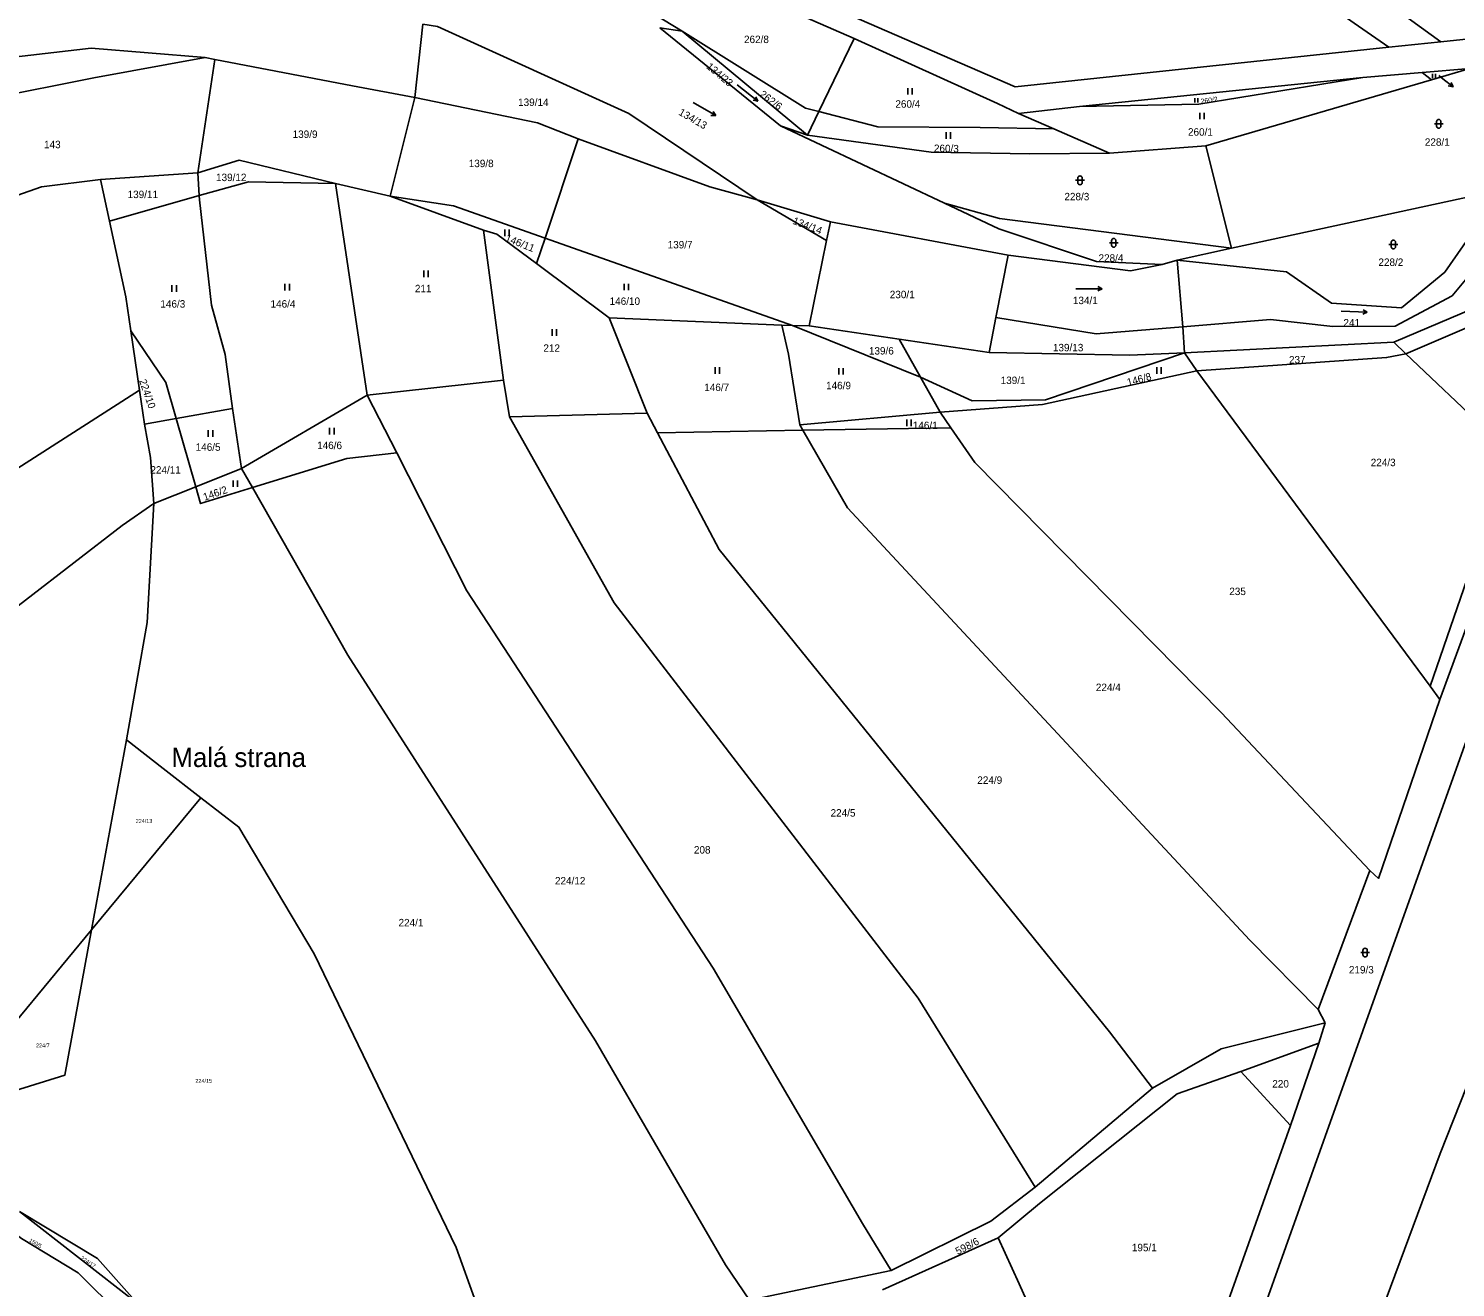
# Model space of a CAD drawing. Extents: x -758582 to -751794, y -998770 to -994350.
# Drawn here: x -755427.1 to -755100.9, y -995507.3 to -995219.5 of the extents above; entities that cross this region are included whole.
import ezdxf

# ---------------------------------------------------------------- set-up
doc = ezdxf.new("R2010")
doc.units = 0
for name, color, linetype in [('Hranice parcel', 7, 'Continuous'), ('Parcelní čísla', 7, 'Continuous'), ('Pop  PČ popisy', 7, 'Continuous'), ('Značky kultur', 7, 'Continuous')]:
    doc.layers.add(name, color=color, linetype=linetype)

msp = doc.modelspace()

# ---------------------------------------------------------------- linework, layer by layer
at = {"layer": 'Hranice parcel'}
for p, q in [((-755138.2, -995197.68), (-755104.25, -995222.48)), ((-755281.37, -995202.97), (-755238.36, -995221.7)), ((-755148.45, -995201.22), (-755116.14, -995223.73)), ((-755277.66, -995220.08), (-755288.3, -995213.59)), ((-755336.91, -995218.43), (-755338.81, -995235.22)), ((-755277.66, -995220.08), (-755282.75, -995219.3)), ((-755255.17, -995241.71), (-755282.75, -995219.3)), ((-755249, -995243.83), (-755277.66, -995220.08)), ((-755238.36, -995221.7), (-755246.41, -995238.44)), ((-755104.25, -995222.48), (-755116.14, -995223.73)), ((-755104.25, -995222.48), (-755094.22, -995221.42)), ((-755384.5, -995226.51), (-755386.67, -995226.04)), ((-755388.37, -995252.43), (-755384.5, -995226.51)), ((-755108.49, -995229.54), (-755097.59, -995228.62)), ((-755097.59, -995228.62), (-755106.35, -995231.18)), ((-755186.86, -995237.28), (-755122.08, -995230.68)), ((-755106.35, -995231.18), (-755157.96, -995246.27)), ((-755122.08, -995230.68), (-755108.49, -995229.54)), ((-755106.35, -995231.18), (-755108.49, -995229.54)), ((-755338.81, -995235.22), (-755344.39, -995257.76)), ((-755246.41, -995238.44), (-755249, -995243.83)), ((-755200.8, -995238.88), (-755186.86, -995237.28)), ((-755200.8, -995238.88), (-755192.72, -995242.36)), ((-755255.17, -995241.71), (-755249, -995243.83)), ((-755217.71, -995259.39), (-755255.17, -995241.71)), ((-755192.72, -995242.36), (-755179.99, -995247.96)), ((-755301.46, -995244.65), (-755309.01, -995267.34)), ((-755157.96, -995246.27), (-755179.99, -995247.96)), ((-755157.96, -995246.27), (-755152.13, -995269.63)), ((-755410.64, -995253.98), (-755388.37, -995252.43)), ((-755410.64, -995253.98), (-755408.59, -995263.5)), ((-755388.04, -995257.66), (-755388.37, -995252.43)), ((-755344.39, -995257.76), (-755356.93, -995254.85)), ((-755356.93, -995254.85), (-755349.65, -995303.26)), ((-755408.59, -995263.5), (-755388.04, -995257.66)), ((-755323.05, -995265.54), (-755344.39, -995257.76)), ((-755260.53, -995258.59), (-755243.78, -995263.63)), ((-755260.53, -995258.59), (-755244.66, -995267.92)), ((-755152.13, -995269.63), (-755090.2, -995256.29)), ((-755243.78, -995263.63), (-755244.66, -995267.92)), ((-755203.15, -995271.29), (-755243.78, -995263.63)), ((-755318.51, -995299.84), (-755323.05, -995265.54)), ((-755309.01, -995267.34), (-755310.94, -995273.14)), ((-755309.01, -995267.34), (-755252.47, -995287.33)), ((-755244.66, -995267.92), (-755248.65, -995287.44)), ((-755203.15, -995271.29), (-755205.95, -995285.55)), ((-755152.13, -995269.63), (-755164.5, -995272.4)), ((-755310.94, -995273.14), (-755294.35, -995285.57)), ((-755164.5, -995272.4), (-755167.97, -995273.36)), ((-755163.21, -995287.65), (-755164.5, -995272.4)), ((-755075.23, -995277.94), (-755112.26, -995293.8)), ((-755294.35, -995285.57), (-755285.63, -995307.39)), ((-755254.89, -995287.26), (-755294.35, -995285.57)), ((-755252.47, -995287.33), (-755254.89, -995287.26)), ((-755248.65, -995287.44), (-755252.47, -995287.33)), ((-755252.47, -995287.33), (-755223.2, -995299.17)), ((-755248.65, -995287.44), (-755228.07, -995290.49)), ((-755207.49, -995293.54), (-755205.95, -995285.55)), ((-755163.21, -995287.65), (-755162.85, -995293.6)), ((-755403.73, -995288.57), (-755401.75, -995302.11)), ((-755207.49, -995293.54), (-755228.07, -995290.49)), ((-755228.07, -995290.49), (-755223.2, -995299.17)), ((-755162.85, -995293.6), (-755114.99, -995291.17)), ((-755114.99, -995291.17), (-755112.26, -995293.8)), ((-755160.05, -995297.73), (-755162.85, -995293.6)), ((-755088.35, -995316.54), (-755112.26, -995293.8)), ((-755160.05, -995297.73), (-755106.72, -995369.78)), ((-755318.51, -995299.84), (-755349.65, -995303.26)), ((-755317.12, -995308.23), (-755318.51, -995299.84)), ((-755223.2, -995299.17), (-755218.7, -995307.19)), ((-755400.56, -995309.88), (-755401.75, -995302.11)), ((-755378.38, -995320), (-755349.65, -995303.26)), ((-755349.65, -995303.26), (-755342.92, -995316.48)), ((-755393.35, -995308.6), (-755380.44, -995306.3)), ((-755380.44, -995306.3), (-755378.38, -995320)), ((-755285.63, -995307.39), (-755317.12, -995308.23)), ((-755283.27, -995311.87), (-755285.63, -995307.39)), ((-755218.7, -995307.19), (-755250.8, -995310.02)), ((-755216.26, -995310.71), (-755218.7, -995307.19)), ((-755400.56, -995309.88), (-755393.35, -995308.6)), ((-755393.35, -995308.6), (-755388.86, -995324.21)), ((-755250.8, -995310.02), (-755250.07, -995311.3)), ((-755250.07, -995311.3), (-755216.26, -995310.71)), ((-755283.27, -995311.87), (-755250.07, -995311.3)), ((-755088.35, -995316.54), (-755106.72, -995369.78)), ((-755378.38, -995320), (-755388.86, -995324.21)), ((-755375.89, -995324.38), (-755378.38, -995320)), ((-755388.86, -995324.21), (-755398.45, -995328.05)), ((-755106.72, -995369.78), (-755104.45, -995372.84)), ((-755412.7, -995425.52), (-755404.72, -995382.03)), ((-755412.7, -995425.52), (-755387.69, -995395.29)), ((-755132.27, -995443.67), (-755120.5, -995411.95)), ((-755447.51, -995467.61), (-755412.7, -995425.52)), ((-755132.27, -995443.67), (-755130.65, -995446.73)), ((-755130.65, -995446.73), (-755132.12, -995451.42)), ((-755132.12, -995451.42), (-755149.99, -995457.85)), ((-755138.62, -995470.24), (-755132.12, -995451.42)), ((-755138.62, -995470.24), (-755149.99, -995457.85)), ((-755196.94, -995484.36), (-755170.15, -995461.71)), ((-755402.15, -995510.9), (-755429.12, -995489.9)), ((-755205.44, -995495.89), (-755231.9, -995507.79)), ((-755262.26, -995510.17), (-755229.88, -995503.41))]:
    msp.add_line(p, q, dxfattribs=at)
for points in [[(-754943.06, -994969.66), (-754967.69, -995048.28), (-754981.66, -995093.48), (-755011.57, -995216.42), (-755037.85, -995310.99), (-755071.06, -995392.36), (-755104.38, -995476.59), (-755151.55, -995603.6), (-755174.64, -995666.61), (-755197.14, -995739.97)], [(-754943.06, -994969.66), (-754967.69, -995048.28), (-754981.66, -995093.48), (-755011.57, -995216.42), (-755037.85, -995310.99), (-755071.06, -995392.36), (-755104.38, -995476.59), (-755151.55, -995603.6), (-755174.64, -995666.61), (-755197.14, -995739.97)], [(-755116.14, -995223.73), (-755201.55, -995232.75), (-755278.62, -995199.27)], [(-755336.91, -995218.43), (-755333.62, -995218.99), (-755289.88, -995238.9), (-755260.53, -995258.59)], [(-755246.41, -995238.44), (-755249.47, -995237.65), (-755277.66, -995220.08)], [(-755238.36, -995221.7), (-755205.56, -995236.59), (-755200.8, -995238.88)], [(-755386.67, -995226.04), (-755412.78, -995223.97), (-755437.13, -995226.79), (-755445.78, -995230.58), (-755481.13, -995251.3)], [(-755386.67, -995226.04), (-755412.19, -995230.76), (-755435.93, -995235.45), (-755460.26, -995245.87)], [(-755338.81, -995235.22), (-755353.02, -995232.52), (-755384.5, -995226.51)], [(-755122.08, -995230.68), (-755159.6, -995236.72), (-755186.86, -995237.28)], [(-755301.46, -995244.65), (-755310.75, -995241.03), (-755338.81, -995235.22)], [(-755192.72, -995242.36), (-755209.55, -995242.09), (-755232.96, -995241.89), (-755246.41, -995238.44)], [(-755056.45, -995237.99), (-755051.24, -995250.07), (-755104.44, -995399.19), (-755157.3, -995547.38), (-755207.11, -995681.84), (-755214.23, -995690.58), (-755216.93, -995699.04), (-755234.29, -995743.7), (-755236.49, -995749.37)], [(-755260.53, -995258.59), (-755271.36, -995255.66), (-755301.46, -995244.65)], [(-755179.99, -995247.96), (-755198.23, -995248.08), (-755220.72, -995247.72), (-755249, -995243.83)], [(-755388.37, -995252.43), (-755378.95, -995249.51), (-755356.93, -995254.85)], [(-755449.56, -995264.56), (-755424.12, -995255.64), (-755410.64, -995253.98)], [(-755388.04, -995257.66), (-755376.78, -995254.46), (-755356.93, -995254.85)], [(-755073.97, -995252.79), (-755083.39, -995258.58), (-755101.65, -995280.54), (-755114.67, -995287.5), (-755128.93, -995287.57), (-755143.16, -995285.94), (-755163.21, -995287.65)], [(-755380.44, -995306.3), (-755382.12, -995293.99), (-755385.29, -995282.66), (-755387.98, -995258.59), (-755388.04, -995257.66)], [(-755344.39, -995257.76), (-755329.95, -995259.99), (-755309.01, -995267.34)], [(-755164.5, -995272.4), (-755139.52, -995275.05), (-755129.21, -995282.24), (-755113.2, -995283.28), (-755103.35, -995275.12), (-755090.2, -995256.29)], [(-755217.71, -995259.39), (-755205.13, -995262.89), (-755152.13, -995269.63)], [(-755167.97, -995273.36), (-755182.96, -995272.7), (-755205.29, -995265.25), (-755217.71, -995259.39)], [(-755401.75, -995302.11), (-755494.82, -995361.79), (-755475.68, -995301.95), (-755472.86, -995296.26), (-755441.79, -995281.92), (-755449.56, -995264.56)], [(-755408.59, -995263.5), (-755404.87, -995280.81), (-755403.73, -995288.57)], [(-755323.05, -995265.54), (-755320.05, -995266.43), (-755310.94, -995273.14)], [(-755167.97, -995273.36), (-755175.18, -995274.83), (-755203.15, -995271.29)], [(-755114.99, -995291.17), (-755081.26, -995276.83), (-755066.92, -995270.03)], [(-755250.8, -995310.02), (-755253.38, -995293.88), (-755254.89, -995287.26)], [(-755205.95, -995285.55), (-755183.06, -995289.28), (-755163.21, -995287.65)], [(-755403.73, -995288.57), (-755395.72, -995300.35), (-755393.35, -995308.6)], [(-755223.2, -995299.17), (-755211.37, -995304.56), (-755194.63, -995304.34), (-755162.85, -995293.6)], [(-755162.85, -995293.6), (-755175.33, -995294.14), (-755207.49, -995293.54)], [(-755112.26, -995293.8), (-755116.63, -995294.68), (-755160.05, -995297.73)], [(-755160.05, -995297.73), (-755195.27, -995305.4), (-755218.7, -995307.19)], [(-755398.45, -995328.05), (-755399.21, -995317.52), (-755400.56, -995309.88)], [(-755196.94, -995484.36), (-755223.71, -995441.14), (-755293.23, -995350.74), (-755317.12, -995308.23)], [(-755120.5, -995411.95), (-755154.35, -995375.88), (-755210.76, -995318.63), (-755216.26, -995310.71)], [(-755170.15, -995461.71), (-755179.95, -995448.81), (-755269.24, -995338.52), (-755283.27, -995311.87)], [(-755250.07, -995311.3), (-755239.85, -995329.04), (-755147.89, -995427.83), (-755132.27, -995443.67)], [(-755375.89, -995324.38), (-755354.31, -995317.71), (-755342.92, -995316.48)], [(-755342.92, -995316.48), (-755326.86, -995348), (-755270.61, -995434.29), (-755236.43, -995492.62), (-755229.88, -995503.41)], [(-755104.45, -995372.84), (-755086.56, -995324.17), (-755085.43, -995319.32)], [(-755388.86, -995324.21), (-755387.76, -995328.05), (-755375.89, -995324.38)], [(-755262.26, -995510.17), (-755267.73, -995502.08), (-755297.47, -995450.87), (-755354.08, -995362.72), (-755375.89, -995324.38)], [(-755398.45, -995328.05), (-755405.66, -995333.09), (-755438.91, -995358.7), (-755458.58, -995379.61), (-755474.86, -995407.56), (-755482.41, -995435.15)], [(-755398.45, -995328.05), (-755399.97, -995355.21), (-755404.72, -995382.03)], [(-755120.5, -995411.95), (-755118.53, -995413.73), (-755104.45, -995372.84)], [(-755404.72, -995382.03), (-755396.32, -995388.62), (-755387.69, -995395.29)], [(-755387.69, -995395.29), (-755378.97, -995402.02), (-755361.77, -995431), (-755329.34, -995498.11), (-755324.84, -995510.64), (-755322.33, -995518.58)], [(-755447.51, -995467.61), (-755418.79, -995458.73), (-755412.7, -995425.52)], [(-755170.15, -995461.71), (-755154.43, -995452.73), (-755130.65, -995446.73)], [(-755149.99, -995457.85), (-755164.52, -995462.99), (-755196.02, -995488.06), (-755205.44, -995495.89)], [(-755173.6, -995565.93), (-755171.5, -995562.97), (-755138.62, -995470.24)], [(-755400.52, -995520.87), (-755406, -995513.61), (-755415.72, -995503.88), (-755428.72, -995496.05), (-755447.12, -995482.53), (-755449.92, -995476.54)], [(-755229.88, -995503.41), (-755207.09, -995492.07), (-755196.94, -995484.36)], [(-755429.12, -995489.9), (-755411.34, -995500.66), (-755402.15, -995510.9)], [(-755205.44, -995495.89), (-755200.65, -995506.41), (-755179.45, -995553.6), (-755173.6, -995565.93)]]:
    msp.add_lwpolyline(points, dxfattribs=at)
at = {"layer": 'Pop  PČ popisy'}
for p, q in [((-755104.73, -995230.16), (-755103.79, -995230.92)), ((-755103.79, -995230.92), (-755101.46, -995232.81)), ((-755101.46, -995232.81), (-755102.55, -995232.57)), ((-755101.46, -995232.81), (-755101.92, -995231.79))]:
    msp.add_line(p, q, dxfattribs=at)
at = {"layer": 'Značky kultur'}
for p, q in [((-755265.09, -995232.36), (-755260.36, -995236.05)), ((-755106.13, -995230.82), (-755106.13, -995229.82)), ((-755105.46, -995230.82), (-755105.46, -995229.82)), ((-755260.36, -995236.05), (-755261.44, -995235.85)), ((-755260.36, -995236.05), (-755260.82, -995235.06)), ((-755226.09, -995234.56), (-755226.09, -995233.06)), ((-755225.09, -995234.56), (-755225.09, -995233.06)), ((-755160.47, -995236.35), (-755160.47, -995235.34)), ((-755159.8, -995236.35), (-755159.8, -995235.34)), ((-755275.19, -995236.36), (-755269.99, -995239.36)), ((-755269.99, -995239.36), (-755270.59, -995238.43)), ((-755159.34, -995240.21), (-755159.34, -995238.71)), ((-755158.34, -995240.21), (-755158.34, -995238.71)), ((-755269.99, -995239.36), (-755271.09, -995239.3)), ((-755105.73, -995241.24), (-755103.73, -995241.24)), ((-755105.23, -995240.74), (-755105.23, -995241.74)), ((-755104.23, -995241.74), (-755104.23, -995240.74)), ((-755217.31, -995244.67), (-755217.31, -995243.17)), ((-755216.31, -995244.67), (-755216.31, -995243.17)), ((-755187.73, -995254.15), (-755185.73, -995254.15)), ((-755187.23, -995253.65), (-755187.23, -995254.65)), ((-755186.23, -995254.65), (-755186.23, -995253.65)), ((-755318.21, -995266.89), (-755318.21, -995265.39)), ((-755317.21, -995266.89), (-755317.21, -995265.39)), ((-755180.01, -995268.45), (-755178.01, -995268.45)), ((-755179.51, -995267.95), (-755179.51, -995268.95)), ((-755178.51, -995268.95), (-755178.51, -995267.95)), ((-755115.6, -995268.32), (-755115.6, -995269.32)), ((-755114.6, -995269.32), (-755114.6, -995268.32)), ((-755116.1, -995268.82), (-755114.1, -995268.82)), ((-755336.72, -995276.27), (-755336.72, -995274.77)), ((-755335.72, -995276.27), (-755335.72, -995274.77)), ((-755394.29, -995279.63), (-755394.29, -995278.13)), ((-755393.29, -995279.63), (-755393.29, -995278.13)), ((-755368.46, -995279.33), (-755368.46, -995277.83)), ((-755367.46, -995279.33), (-755367.46, -995277.83)), ((-755290.91, -995279.3), (-755290.91, -995277.8)), ((-755289.91, -995279.3), (-755289.91, -995277.8)), ((-755187.68, -995278.93), (-755181.68, -995278.93)), ((-755181.68, -995278.93), (-755182.66, -995278.43)), ((-755181.68, -995278.93), (-755182.66, -995279.43)), ((-755127.04, -995284.08), (-755121.05, -995284.29)), ((-755121.05, -995284.29), (-755122.04, -995284.76)), ((-755121.05, -995284.29), (-755122, -995283.76)), ((-755307.36, -995289.71), (-755307.36, -995288.21)), ((-755306.36, -995289.71), (-755306.36, -995288.21)), ((-755270.14, -995298.36), (-755270.14, -995296.86)), ((-755269.14, -995298.36), (-755269.14, -995296.86)), ((-755241.88, -995298.58), (-755241.88, -995297.08)), ((-755240.88, -995298.58), (-755240.88, -995297.08)), ((-755169.15, -995298.37), (-755169.15, -995296.87)), ((-755168.15, -995298.37), (-755168.15, -995296.87)), ((-755358.25, -995312.27), (-755358.25, -995310.77)), ((-755357.25, -995312.27), (-755357.25, -995310.77)), ((-755226.31, -995310.36), (-755226.31, -995308.86)), ((-755225.31, -995310.36), (-755225.31, -995308.86)), ((-755385.98, -995312.76), (-755385.98, -995311.26)), ((-755384.98, -995312.76), (-755384.98, -995311.26)), ((-755380.28, -995324.25), (-755380.28, -995322.75)), ((-755379.28, -995324.25), (-755379.28, -995322.75)), ((-755122.55, -995430.69), (-755120.55, -995430.69)), ((-755122.05, -995430.19), (-755122.05, -995431.19)), ((-755121.05, -995431.19), (-755121.05, -995430.19))]:
    msp.add_line(p, q, dxfattribs=at)
for centre, start, end in [((-755104.73, -995240.74), 0, 180), ((-755104.73, -995241.74), 180, 359.9879), ((-755186.73, -995253.65), 0, 180), ((-755186.73, -995254.65), 180, 359.9879), ((-755179.01, -995267.95), 0, 180), ((-755115.1, -995268.32), 0, 180), ((-755179.01, -995268.95), 180, 359.9879), ((-755115.1, -995269.32), 180, 359.9879), ((-755121.55, -995430.19), 0, 180), ((-755121.55, -995431.19), 180, 359.9879)]:
    msp.add_arc(centre, 0.5, start, end, dxfattribs=at)

# ---------------------------------------------------------------- texts
at = {"layer": 'Parcelní čísla'}
for s, height, p in [('262/8', 1.7, (-755263.53, -995222.78)), ('139/14', 1.7, (-755315.17, -995237.15)), ('260/4', 1.7, (-755228.93, -995237.55)), ('260/1', 1.7, (-755162.04, -995243.94)), ('143', 1.7, (-755423.53, -995246.81)), ('139/9', 1.7, (-755366.71, -995244.46)), ('228/1', 1.7, (-755107.9, -995246.26)), ('139/8', 1.7, (-755326.45, -995251.14)), ('139/12', 1.7, (-755384.22, -995254.33)), ('139/11', 1.7, (-755404.43, -995258.22)), ('228/3', 1.7, (-755190.29, -995258.72)), ('139/7', 1.7, (-755280.98, -995269.72)), ('228/4', 1.7, (-755182.49, -995272.76)), ('228/2', 1.7, (-755118.51, -995273.72)), ('211', 1.7, (-755338.76, -995279.74)), ('146/3', 1.7, (-755396.94, -995283.25)), ('146/4', 1.7, (-755371.76, -995283.25)), ('146/10', 1.7, (-755294.25, -995282.63)), ('230/1', 1.7, (-755230.21, -995281.1)), ('134/1', 1.7, (-755188.36, -995282.46)), ('241', 1.7, (-755126.51, -995287.56)), ('212', 1.7, (-755309.39, -995293.36)), ('139/6', 1.7, (-755234.98, -995293.98)), ('139/13', 1.7, (-755192.92, -995293.24)), ('146/7', 1.7, (-755272.62, -995302.33)), ('146/9', 1.7, (-755244.77, -995301.91)), ('139/1', 1.7, (-755204.86, -995300.72)), ('146/1', 1.7, (-755224.95, -995311.03)), ('146/6', 1.7, (-755361.11, -995315.6)), ('146/5', 1.7, (-755388.87, -995315.98)), ('224/11', 1.7, (-755399.22, -995321.2)), ('224/3', 1.7, (-755120.27, -995319.5)), ('235', 1.7, (-755152.6, -995348.97)), ('224/4', 1.7, (-755183.1, -995370.91)), ('224/9', 1.7, (-755210.2, -995392.12)), ('224/5', 1.7, (-755243.74, -995399.61)), ('224/13', 0.9, (-755402.58, -995401.07)), ('208', 1.7, (-755274.98, -995408.06)), ('224/12', 1.7, (-755306.74, -995415.12)), ('224/1', 1.7, (-755342.5, -995424.7)), ('219/3', 1.7, (-755125.26, -995435.47)), ('224/7', 0.9, (-755425.36, -995452.38)), ('224/15', 0.9, (-755388.93, -995460.47)), ('220', 1.7, (-755142.77, -995461.54)), ('195/1', 1.7, (-755174.87, -995498.97))]:
    msp.add_text(s, height=height, dxfattribs=at).set_placement(p)
for s, height, rotation, p in [('134/23', 1.7, 320, (-755272.28, -995228.39)), ('262/6', 1.7, 323, (-755260.15, -995234.8)), ('260/2', 1.14, 8, (-755159.07, -995236.67)), ('134/13', 1.7, 330, (-755278.64, -995239.07)), ('260/3', 1.7, 359, (-755220.13, -995247.67)), ('134/14', 1.7, 339, (-755252.56, -995264.05)), ('146/11', 1.7, 338, (-755318.26, -995267.98)), ('237', 1.7, 1, (-755138.94, -995296.04)), ('224/10', 1.7, 289, (-755401.83, -995299.93)), ('146/8', 1.7, 15, (-755175.75, -995301.2)), ('146/2', 1.7, 19, (-755386.83, -995327.42)), ('150/5', 0.9, 330, (-755427.04, -995496.75)), ('598/6', 1.7, 27, (-755214.67, -995499.85)), ('224/17', 0.9, 327, (-755415.29, -995500.77))]:
    msp.add_text(s, height=height, rotation=rotation, dxfattribs=at).set_placement(p)
at = {"layer": 'Pop  PČ popisy'}
msp.add_text('Malá strana', height=4.4, dxfattribs=at).set_placement((-755394.4, -995388.28))

doc.saveas('drawing.dxf')
